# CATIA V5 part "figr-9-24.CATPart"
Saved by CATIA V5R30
Part number: Part2
Bounding box of the stored display mesh (mm): x -72 to 72, y -80 to 90, z -20 to 41.296
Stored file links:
  D:\PROJECTS\CATIA V56R 2020\Resources\Parts File\c09_catia_v5_6r2020_prt\figr-9-24.CATPart
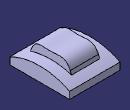
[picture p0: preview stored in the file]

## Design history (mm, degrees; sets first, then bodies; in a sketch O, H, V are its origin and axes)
Body1 (main body)
  Sketch1 on yz-plane, origin (0, 0, 0), H (0, 1, 0), V (0, 0, 1)
    arc A1 centre (5, -170) radius 190.0658 from (-80, 0) to (90, 0) cw
    point P2 (-80, 0)
    point P3 (0, 20)
    line L1 (-80, 0) -> (-80, -20)
    line L2 (-80, -20) -> (90, -20)
    line L3 (90, -20) -> (90, 0)
    coincidence: P2 H, A1 P3, P3 V
    vertical: L1 V, L3 V
    horizontal: L2 H
  Pad1: profile Sketch1, direction (1, 0, 0), length 72, mirrored extent
  Sketch2 on yz-plane, origin (0, 0, 0), H (0, 1, 0), V (0, 0, 1)
    spline S1 through (60, 20) (40, 40) (10, 40) (-10, 40) (-30, 40) (-50, 20)
  Sketch3 on zx-plane, origin (0, 0, 0), H (-1, 0, 0), V (0, 0, 1)
    line L1 (-40, 30) -> (40, 30)
    horizontal: L1 H
  Rib1: profile Sketch2, centre curve Sketch3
